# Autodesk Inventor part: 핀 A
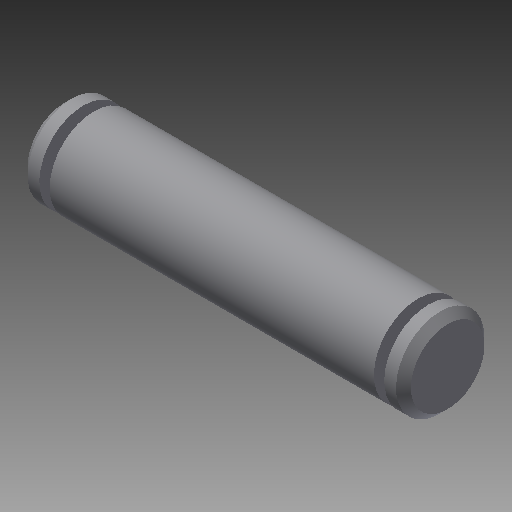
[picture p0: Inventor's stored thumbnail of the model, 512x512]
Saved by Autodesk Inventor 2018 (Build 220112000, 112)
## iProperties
Created: 2020-02
Part Number: 핀 A
Material: 스테인리스강
Document SubType Name: Modeling
Designer: mduedu
Density: 1 g/cm^3
Appearance: 기본값
Author: mduedu
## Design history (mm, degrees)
sketch "스케치1"
  geometry: L1 (0, 0)-(26, 0); L2 (26, 0)-(26, 3); L3 (26, 3)-(0, 3); L4 (0, 3)-(0, 0)
  constraints: 8 end point, 2 parallel, 1 horizontal, 1 perpendicular
  dimensions: "d0" = 26 distance of L2.end L3.end; "d2" = 6 diameter of L3 L1
revolve "회전1" sketch "스케치1" stored, may be unused: angle "d3" = 90 deg
sketch "스케치2"
  geometry: L1 (0, -3)-(0, 3) reference; L2 (0, 3)-(26, 3) reference; L3 (26, 3)-(26, -3) reference; L4 (26, -3)-(0, -3) reference; L5 (0, 0)-(26, 0); L6 (1.3, 3)-(2, 3); L7 (2, 3)-(2, 2); L8 (2, 2)-(1.3, 2); L9 (1.3, 2)-(1.3, 3)
  constraints: 10 end point, 2 parallel, 1 horizontal, 1 midpoint, 1 perpendicular, 1 point on line
  dimensions: "d4" = 4 diameter of L8 L5; "d6" = 1.3 distance between parallel lines of L9 L1; "d7" = 0.7 distance between parallel lines of L7 L9
revolve "회전2" sketch "스케치2" stored, may be unused: angle "d8" = 90 deg
node "작업 평면1"
chamfer "모따기1" distance "d9" = 0.5; stored, may be unused: second distance "d10" = 2, angle "d11" = 45 deg
node "솔리드1"
mirror "대칭1"
node "절단 모서리 투영1"
